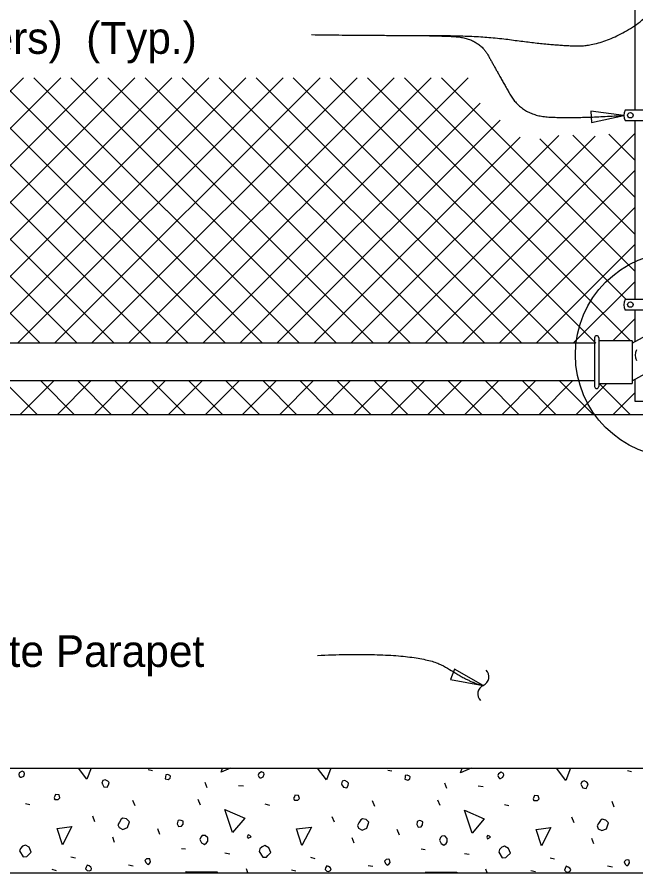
# Model space of a CAD drawing. Extents: x 0.4 to 38.5, y 1.2 to 25.4.
# Drawn here: x 7.87 to 11.81, y 14.04 to 19.49 of the extents above; entities that cross this region are included whole.
import ezdxf

# ---------------------------------------------------------------- set-up
doc = ezdxf.new("R2010")
doc.units = 0
for name, color, linetype in [('Dimension', 7, 'Continuous'), ('Miscellaneous', 7, 'Continuous'), ('SteelMisc', 7, 'Continuous'), ('SupstrConc', 7, 'Continuous'), ('TextStructures', 7, 'Continuous')]:
    doc.layers.add(name, color=color, linetype=linetype)

msp = doc.modelspace()

# ---------------------------------------------------------------- linework, layer by layer
at = {"layer": 'Dimension'}
for points in [[(11.7316, 18.8606), (11.522, 18.8867), (11.5251, 18.8162)], [(10.8378, 15.2332), (10.6542, 15.3377), (10.6301, 15.2714)]]:
    msp.add_lwpolyline(points, close=True, dxfattribs=at)
msp.add_circle((12.0765, 17.337), 0.6527, dxfattribs=at)
for centre, start, end in [((10.8136, 15.2881), 294.1466, 45.8738), ((10.8624, 15.1793), 114.1466, 225.8738)]:
    msp.add_arc(centre, 0.0596, start, end, dxfattribs=at)
for points in [[(10.3869, 19.3682), (10.7834, 19.3742), (11.2324, 19.311), (11.5936, 19.2943), (12.0146, 19.5727), (12.0178, 19.9637)], [(9.7456, 19.3742), (10.1209, 19.3697), (10.4814, 19.3697), (10.8059, 19.3561), (10.9319, 19.1279), (11.0853, 18.8591), (11.4256, 18.8409), (11.7316, 18.8606)], [(9.7834, 15.4246), (10.44, 15.453), (10.7614, 15.2449), (10.838, 15.2337)]]:
    msp.add_open_spline(points, degree=2, dxfattribs=at)
at = {"layer": 'Miscellaneous'}
for p, q in [((8.0185, 17.4104), (2.8414, 22.5875)), ((8.2542, 17.4104), (3.0771, 22.5875)), ((8.4899, 17.4104), (3.3128, 22.5875)), ((8.7256, 17.4104), (3.5485, 22.5875)), ((8.9613, 17.4104), (3.7842, 22.5875)), ((7.914, 19.0998), (6.2246, 17.4104)), ((8.1497, 19.0998), (6.4603, 17.4104)), ((8.3854, 19.0998), (6.696, 17.4104)), ((8.6211, 19.0998), (6.9317, 17.4104)), ((8.8568, 19.0998), (7.1674, 17.4104)), ((9.0925, 19.0998), (7.4031, 17.4104)), ((9.197, 17.4104), (7.5077, 19.0998)), ((9.3282, 19.0998), (7.6388, 17.4104)), ((9.4327, 17.4104), (7.7434, 19.0998)), ((9.5639, 19.0998), (7.8745, 17.4104)), ((9.6684, 17.4104), (7.9791, 19.0998)), ((9.7996, 19.0998), (8.1102, 17.4104)), ((9.9041, 17.4104), (8.2148, 19.0998)), ((10.0353, 19.0998), (8.3459, 17.4104)), ((10.1398, 17.4104), (8.4505, 19.0998)), ((10.271, 19.0998), (8.5816, 17.4104)), ((10.3756, 17.4104), (8.6862, 19.0998)), ((10.5067, 19.0998), (8.8173, 17.4104)), ((10.6113, 17.4104), (8.9219, 19.0998)), ((10.7424, 19.0998), (9.053, 17.4104)), ((10.847, 17.4104), (9.1576, 19.0998)), ((11.0827, 17.4104), (9.3933, 19.0998)), ((11.3184, 17.4104), (9.629, 19.0998)), ((11.5541, 17.4104), (9.8647, 19.0998)), ((11.7743, 17.4258), (10.1004, 19.0998)), ((11.7421, 17.6937), (10.3361, 19.0998)), ((11.8042, 17.8674), (10.5718, 19.0998)), ((10.8171, 18.9388), (9.2887, 17.4104)), ((10.9449, 18.8308), (9.5244, 17.4104)), ((11.318, 18.7325), (9.9958, 17.4104)), ((11.8042, 18.7473), (10.4672, 17.4104)), ((11.8042, 18.3388), (11.4082, 18.7348)), ((11.8042, 18.5745), (11.6373, 18.7413)), ((11.0726, 18.7229), (9.7601, 17.4104)), ((11.5495, 18.7283), (10.2315, 17.4104)), ((11.8042, 18.1031), (11.1967, 18.7105)), ((11.8042, 18.5116), (10.7029, 17.4104)), ((11.8042, 18.2759), (10.9386, 17.4104)), ((11.8042, 18.0402), (11.1743, 17.4104)), ((11.8042, 17.8045), (11.41, 17.4104)), ((11.8042, 17.5688), (11.6612, 17.4258)), ((8.0002, 16.9573), (7.7867, 17.1708)), ((8.1063, 17.1708), (7.8928, 16.9573)), ((8.2359, 16.9573), (8.0224, 17.1708)), ((8.342, 17.1708), (8.1285, 16.9573)), ((8.4716, 16.9573), (8.2581, 17.1708)), ((8.5777, 17.1708), (8.3642, 16.9573)), ((8.7073, 16.9573), (8.4938, 17.1708)), ((8.8134, 17.1708), (8.5999, 16.9573)), ((8.943, 16.9573), (8.7295, 17.1708)), ((9.0491, 17.1708), (8.8356, 16.9573)), ((9.1788, 16.9573), (8.9652, 17.1708)), ((9.2848, 17.1708), (9.0713, 16.9573)), ((9.4145, 16.9573), (9.2009, 17.1708)), ((9.5205, 17.1708), (9.307, 16.9573)), ((9.6502, 16.9573), (9.4366, 17.1708)), ((9.7562, 17.1708), (9.5427, 16.9573)), ((9.8859, 16.9573), (9.6723, 17.1708)), ((9.9919, 17.1708), (9.7784, 16.9573)), ((10.1216, 16.9573), (9.908, 17.1708)), ((10.2276, 17.1708), (10.0141, 16.9573)), ((10.3573, 16.9573), (10.1437, 17.1708)), ((10.4633, 17.1708), (10.2498, 16.9573)), ((10.593, 16.9573), (10.3794, 17.1708)), ((10.6991, 17.1708), (10.4855, 16.9573)), ((10.8287, 16.9573), (10.6151, 17.1708)), ((10.9348, 17.1708), (10.7212, 16.9573)), ((11.0644, 16.9573), (10.8508, 17.1708)), ((11.1705, 17.1708), (10.9569, 16.9573)), ((11.3001, 16.9573), (11.0865, 17.1708)), ((11.4062, 17.1708), (11.1926, 16.9573)), ((11.5358, 16.9573), (11.3222, 17.1708)), ((11.6246, 17.1536), (11.4283, 16.9573)), ((11.7715, 16.9573), (11.5752, 17.1536)), ((11.8042, 17.0974), (11.664, 16.9573)), ((8.7067, 14.6982), (8.7332, 14.6929)), ((10.2305, 14.6946), (10.257, 14.6893)), ((11.7543, 14.6911), (11.7808, 14.6858)), ((9.0815, 14.5815), (9.0691, 14.6151)), ((9.2812, 14.5974), (9.313, 14.5939)), ((10.6053, 14.578), (10.5929, 14.6116)), ((10.805, 14.5939), (10.8368, 14.5904)), ((8.6236, 14.4666), (8.6095, 14.502)), ((9.039, 14.4719), (9.0249, 14.5073)), ((10.1474, 14.4631), (10.1333, 14.4984)), ((10.5628, 14.4684), (10.5487, 14.5037)), ((11.6712, 14.4595), (11.6571, 14.4949)), ((7.9253, 14.4825), (7.9536, 14.4754)), ((9.4491, 14.479), (9.4774, 14.4719)), ((10.973, 14.4754), (11.0012, 14.4684)), ((8.3673, 14.3658), (8.3531, 14.4012)), ((9.8911, 14.3623), (9.8769, 14.3977)), ((11.4149, 14.3588), (11.4008, 14.3941)), ((8.4928, 14.2333), (8.4804, 14.2668)), ((8.7809, 14.2845), (8.7668, 14.3199)), ((10.3047, 14.281), (10.2906, 14.3163)), ((10.0166, 14.2297), (10.0042, 14.2633)), ((11.5404, 14.2262), (11.528, 14.2598)), ((8.9188, 14.1961), (8.9436, 14.1926)), ((9.1946, 14.1679), (9.2246, 14.1626)), ((10.4426, 14.1926), (10.4674, 14.1891)), ((10.7184, 14.1643), (10.7485, 14.159)), ((8.2152, 14.1431), (8.2435, 14.136)), ((9.7391, 14.1396), (9.7673, 14.1325)), ((11.2629, 14.136), (11.2912, 14.129)), ((8.0933, 14.0636), (8.1216, 14.0565)), ((8.5812, 14.0918), (8.6112, 14.0865)), ((9.3405, 14.0406), (9.3307, 14.0671)), ((9.6171, 14.06), (9.6454, 14.0529)), ((10.105, 14.0883), (10.135, 14.083)), ((10.863, 14.0406), (10.8545, 14.0636)), ((11.1409, 14.0565), (11.1692, 14.0494)), ((11.6288, 14.0848), (11.6589, 14.0795))]:
    msp.add_line(p, q, dxfattribs=at)
for points in [[(8.316, 14.6363), (8.2621, 14.7072)], [(8.3425, 14.7072), (8.316, 14.6363)], [(9.1698, 14.6805), (9.1781, 14.7072)], [(9.2293, 14.7072), (9.1698, 14.6805)], [(9.8398, 14.6328), (9.7832, 14.7072)], [(9.8677, 14.7072), (9.8398, 14.6328)], [(10.6937, 14.677), (10.703, 14.7072)], [(10.761, 14.7072), (10.6937, 14.677)], [(11.3636, 14.6292), (11.3044, 14.7072)], [(11.3928, 14.7072), (11.3636, 14.6292)], [(7.8935, 14.6487), (7.9006, 14.6487), (7.9147, 14.6558), (7.92, 14.6717), (7.9183, 14.6805), (7.9041, 14.6876), (7.8864, 14.677), (7.8829, 14.6664), (7.8864, 14.6558), (7.8935, 14.6487)], [(8.8145, 14.6398), (8.834, 14.6345), (8.8463, 14.6434), (8.8481, 14.6558), (8.8446, 14.6593), (8.8304, 14.6664), (8.8181, 14.6646), (8.8163, 14.6522), (8.8145, 14.6398)], [(9.4173, 14.6452), (9.4244, 14.6452), (9.4385, 14.6522), (9.4438, 14.6681), (9.4421, 14.677), (9.4279, 14.684), (9.4103, 14.6734), (9.4067, 14.6628), (9.4103, 14.6522), (9.4173, 14.6452)], [(10.3383, 14.6363), (10.3578, 14.631), (10.3702, 14.6398), (10.3719, 14.6522), (10.3684, 14.6558), (10.3542, 14.6628), (10.3419, 14.6611), (10.3401, 14.6487), (10.3383, 14.6363)], [(10.9411, 14.6416), (10.9482, 14.6416), (10.9624, 14.6487), (10.9677, 14.6646), (10.9659, 14.6734), (10.9517, 14.6805), (10.9341, 14.6699), (10.9305, 14.6593), (10.9341, 14.6487), (10.9411, 14.6416)], [(8.415, 14.6045), (8.4238, 14.5886), (8.4451, 14.585), (8.4539, 14.601), (8.4574, 14.6151), (8.4486, 14.6239), (8.4327, 14.6328), (8.4168, 14.6275), (8.4115, 14.6116), (8.415, 14.6045)], [(9.9388, 14.601), (9.9477, 14.585), (9.9689, 14.5815), (9.9777, 14.5974), (9.9812, 14.6116), (9.9724, 14.6204), (9.9565, 14.6292), (9.9406, 14.6239), (9.9353, 14.608), (9.9388, 14.601)], [(11.4626, 14.5974), (11.4715, 14.5815), (11.4927, 14.578), (11.5015, 14.5939), (11.5051, 14.608), (11.4962, 14.6169), (11.4803, 14.6257), (11.4644, 14.6204), (11.4591, 14.6045), (11.4626, 14.5974)], [(8.1127, 14.5073), (8.1339, 14.5073), (8.1445, 14.5179), (8.1392, 14.5373), (8.1163, 14.5391), (8.1127, 14.5285), (8.1074, 14.5196), (8.1127, 14.5073), (8.1092, 14.5108)], [(9.6365, 14.5037), (9.6577, 14.5037), (9.6684, 14.5143), (9.663, 14.5338), (9.6401, 14.5355), (9.6365, 14.5249), (9.6312, 14.5161), (9.6365, 14.5037), (9.633, 14.5073)], [(11.1603, 14.5002), (11.1816, 14.5002), (11.1922, 14.5108), (11.1869, 14.5302), (11.1639, 14.532), (11.1603, 14.5214), (11.155, 14.5126), (11.1603, 14.5002), (11.1568, 14.5037)], [(9.2423, 14.2969), (9.1946, 14.4436), (9.3201, 14.3888), (9.2423, 14.2969)], [(10.7661, 14.2934), (10.7184, 14.4401), (10.8439, 14.3853), (10.7661, 14.2934)], [(8.5211, 14.3287), (8.5441, 14.3163), (8.5741, 14.3287), (8.5865, 14.3658), (8.5688, 14.3835), (8.5458, 14.3888), (8.5352, 14.3818), (8.5228, 14.3623), (8.514, 14.3464), (8.5211, 14.3287)], [(8.8905, 14.3517), (8.8994, 14.3358), (8.9188, 14.3376), (8.9277, 14.3499), (8.9294, 14.3694), (8.917, 14.3747), (8.9082, 14.3765), (8.8976, 14.3729), (8.8941, 14.3694), (8.8905, 14.3517)], [(10.0449, 14.3252), (10.0679, 14.3128), (10.0979, 14.3252), (10.1103, 14.3623), (10.0926, 14.38), (10.0696, 14.3853), (10.059, 14.3782), (10.0467, 14.3588), (10.0378, 14.3429), (10.0449, 14.3252)], [(11.5687, 14.3216), (11.5917, 14.3093), (11.6217, 14.3216), (11.6341, 14.3588), (11.6164, 14.3765), (11.5934, 14.3818), (11.5828, 14.3747), (11.5705, 14.3552), (11.5616, 14.3393), (11.5687, 14.3216)], [(8.1604, 14.2191), (8.1269, 14.3234), (8.2205, 14.3358), (8.1604, 14.2191)], [(9.6843, 14.2156), (9.6507, 14.3199), (9.7444, 14.3323), (9.6843, 14.2156)], [(10.4143, 14.3482), (10.4232, 14.3323), (10.4426, 14.334), (10.4515, 14.3464), (10.4532, 14.3658), (10.4409, 14.3711), (10.432, 14.3729), (10.4214, 14.3694), (10.4179, 14.3658), (10.4143, 14.3482)], [(11.2081, 14.212), (11.1745, 14.3163), (11.2682, 14.3287), (11.2081, 14.212)], [(9.0355, 14.2527), (9.0461, 14.2315), (9.0638, 14.2209), (9.0779, 14.2315), (9.085, 14.2421), (9.085, 14.2633), (9.0691, 14.2792), (9.0496, 14.2775), (9.0408, 14.2686), (9.0355, 14.2527)], [(9.3413, 14.2615), (9.3608, 14.2704), (9.3537, 14.2775), (9.3413, 14.2828), (9.336, 14.2704), (9.3413, 14.2615)], [(10.5593, 14.2492), (10.5699, 14.228), (10.5876, 14.2174), (10.6017, 14.228), (10.6088, 14.2386), (10.6088, 14.2598), (10.5929, 14.2757), (10.5734, 14.2739), (10.5646, 14.2651), (10.5593, 14.2492)], [(10.8651, 14.258), (10.8846, 14.2668), (10.8775, 14.2739), (10.8651, 14.2792), (10.8598, 14.2668), (10.8651, 14.258)], [(7.8882, 14.1802), (7.9112, 14.1431), (7.9342, 14.1449), (7.943, 14.1537), (7.9625, 14.1732), (7.9501, 14.2032), (7.9253, 14.2174), (7.9077, 14.2103), (7.8935, 14.1961), (7.8882, 14.1802)], [(9.412, 14.1767), (9.435, 14.1396), (9.458, 14.1413), (9.4668, 14.1502), (9.4863, 14.1696), (9.4739, 14.1997), (9.4491, 14.2138), (9.4315, 14.2067), (9.4173, 14.1926), (9.412, 14.1767)], [(10.9358, 14.1732), (10.9588, 14.136), (10.9818, 14.1378), (10.9906, 14.1466), (11.0101, 14.1661), (10.9977, 14.1961), (10.973, 14.2103), (10.9553, 14.2032), (10.9411, 14.1891), (10.9358, 14.1732)], [(8.6925, 14.1042), (8.7031, 14.0936), (8.7138, 14.1007), (8.7208, 14.1113), (8.7173, 14.129), (8.7085, 14.1307), (8.6961, 14.129), (8.6855, 14.1184), (8.6925, 14.1042)], [(10.2164, 14.1007), (10.227, 14.0901), (10.2376, 14.0971), (10.2446, 14.1077), (10.2411, 14.1254), (10.2323, 14.1272), (10.2199, 14.1254), (10.2093, 14.1148), (10.2164, 14.1007)], [(11.7402, 14.0971), (11.7508, 14.0865), (11.7614, 14.0936), (11.7685, 14.1042), (11.7649, 14.1219), (11.7561, 14.1237), (11.7437, 14.1219), (11.7331, 14.1113), (11.7402, 14.0971)], [(8.3178, 14.0547), (8.3302, 14.0529), (8.3425, 14.0583), (8.3461, 14.0689), (8.3408, 14.0777), (8.3302, 14.0848), (8.3178, 14.0901), (8.3107, 14.0759), (8.3072, 14.0653), (8.3178, 14.0547)], [(8.9521, 14.0406), (8.9453, 14.0494), (9.1451, 14.0476), (9.1424, 14.0406)], [(9.8416, 14.0512), (9.854, 14.0494), (9.8663, 14.0547), (9.8699, 14.0653), (9.8646, 14.0742), (9.854, 14.0812), (9.8416, 14.0865), (9.8345, 14.0724), (9.831, 14.0618), (9.8416, 14.0512)], [(11.3654, 14.0476), (11.3778, 14.0459), (11.3902, 14.0512), (11.3937, 14.0618), (11.3884, 14.0706), (11.3778, 14.0777), (11.3654, 14.083), (11.3583, 14.0689), (11.3548, 14.0583), (11.3654, 14.0476)], [(10.4732, 14.0406), (10.4691, 14.0459), (10.6689, 14.0441), (10.6676, 14.0406)]]:
    msp.add_lwpolyline(points, dxfattribs=at)
at = {"layer": 'SteelMisc'}
for p, q in [((11.8042, 18.8942), (11.8042, 20.0313)), ((12.2309, 18.8942), (11.7397, 18.8942)), ((12.2309, 18.8265), (11.7405, 18.8265)), ((11.8042, 17.6895), (11.8042, 18.8265)), ((12.2309, 17.6895), (11.7397, 17.6895)), ((12.2309, 17.6219), (11.7405, 17.6219)), ((11.8042, 17.4214), (11.8042, 17.6219)), ((11.5457, 17.4454), (11.5457, 17.1357)), ((11.5725, 17.4454), (11.5725, 17.1357)), ((11.7855, 17.4258), (11.5725, 17.4258)), ((11.7855, 17.4111), (11.8963, 17.4724)), ((11.7855, 17.4258), (11.7855, 17.1536)), ((11.5457, 17.4104), (2.6043, 17.4104)), ((11.7855, 17.1717), (11.9994, 17.2902)), ((11.5457, 17.1708), (2.6043, 17.1708)), ((11.5725, 17.1536), (11.7855, 17.1536)), ((11.8042, 17.0406), (11.8042, 17.182)), ((11.8667, 17.0406), (11.8042, 17.0406))]:
    msp.add_line(p, q, dxfattribs=at)
for centre, start, end in [((11.5592, 17.4453), 0, 180), ((11.5592, 17.1355), 180, 0)]:
    msp.add_arc(centre, 0.0134, start, end, dxfattribs=at)
for centre, start_param, end_param in [((11.8092, 18.861), 5.821213, 6.75616), ((11.8092, 17.6564), 5.821017, 6.76572), ((11.8818, 17.3345), 5.810211, 6.75616)]:
    msp.add_ellipse(centre, major_axis=(-0.0776, 0), ratio=0.957868, start_param=start_param, end_param=end_param, dxfattribs=at)
for centre in [(11.7734, 18.8614), (11.7734, 17.6568)]:
    msp.add_ellipse(centre, major_axis=(0.0177, 0), ratio=0.957868, dxfattribs=at)
at = {"layer": 'SupstrConc'}
for p, q in [((5.5315, 16.9573), (18.6893, 16.9573)), ((0.6881, 14.7072), (23.462, 14.7072)), ((0.6881, 14.0406), (23.462, 14.0406))]:
    msp.add_line(p, q, dxfattribs=at)

# ---------------------------------------------------------------- texts
at = {"layer": 'TextStructures'}
for s, p in [('Centers)  (Typ.)', (7.1282, 19.2522)), ('Concrete Parapet', (6.9497, 15.351))]:
    msp.add_text(s, height=0.2016, dxfattribs=at).set_placement(p)

doc.saveas('drawing.dxf')
